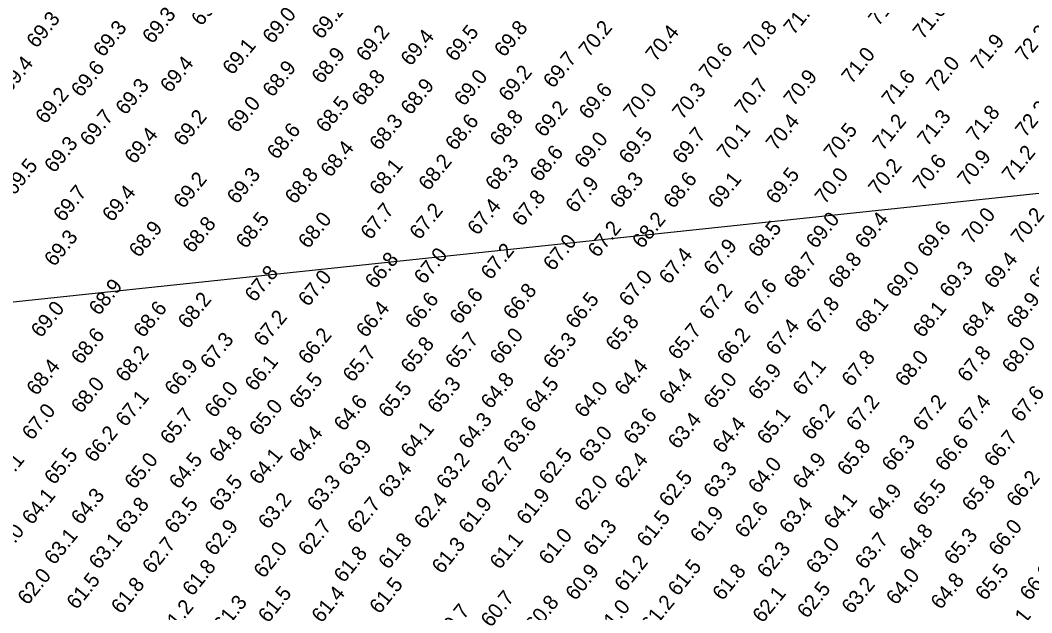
# Model space of a CAD drawing. Extents: x 401290 to 405690, y 1190598 to 1193998.
# Drawn here: x 403181 to 403862, y 1192215 to 1192614 of the extents above; entities that cross this region are included whole.
import ezdxf

# ---------------------------------------------------------------- set-up
doc = ezdxf.new("R2010")
doc.units = 0
doc.layers.add('C-CHAN-CNTR', color=7, linetype='Continuous')
doc.layers.add('V-TOPO-SOUN', color=7, linetype='Continuous')

msp = doc.modelspace()

# ---------------------------------------------------------------- linework, layer by layer
at = {"layer": 'C-CHAN-CNTR'}
msp.add_line((401937.03, 1192293.37), (404340.86, 1192548.17), dxfattribs=at)

# ---------------------------------------------------------------- texts
at = {"layer": 'V-TOPO-SOUN'}
for s, p in [('71.3 ', (403759.2, 1192610.02)), ('69.1 ', (403303.19, 1192610.02)), ('71.0 ', (403702.17, 1192604.02)), ('69.3 ', (403270.19, 1192598.02)), ('69.0 ', (403351.19, 1192598.02)), ('69.2 ', (403384.2, 1192601.04)), ('71.6 ', (403789.18, 1192601.04)), ('69.3 ', (403192.2, 1192595.03)), ('69.3 ', (403237.18, 1192589.03)), ('69.2 ', (403414.18, 1192586.01)), ('69.4 ', (403444.2, 1192583.02)), ('69.5 ', (403474.19, 1192586.01)), ('69.8 ', (403507.2, 1192589.03)), ('70.2 ', (403564.18, 1192589.03)), ('70.4 ', (403609.2, 1192586.01)), ('70.8 ', (403675.17, 1192589.03)), ('72.2 ', (403858.18, 1192586.01)), ('69.1 ', (403324.19, 1192577.02)), ('71.9 ', (403828.19, 1192580)), ('68.9 ', (403384.2, 1192571.02)), ('70.6 ', (403645.19, 1192574.03)), ('71.0 ', (403741.18, 1192571.02)), ('69.4 ', (403174.19, 1192565.01)), ('69.6 ', (403222.19, 1192562.03)), ('69.4 ', (403282.2, 1192565.01)), ('69.7 ', (403540.2, 1192568.03)), ('72.0 ', (403798.17, 1192565.01)), ('68.9 ', (403351.19, 1192562.03)), ('68.8 ', (403411.2, 1192556.02)), ('69.0 ', (403480.19, 1192556.02)), ('69.2 ', (403510.18, 1192559.01)), ('70.9 ', (403702.17, 1192556.02)), ('71.6 ', (403768.19, 1192556.02)), ('69.3 ', (403252.18, 1192550.02)), ('68.9 ', (403444.2, 1192550.02)), ('70.7 ', (403669.2, 1192550.02)), ('69.2 ', (403198.17, 1192544.01)), ('69.6 ', (403564.18, 1192547.03)), ('70.0 ', (403594.2, 1192547.03)), ('70.3 ', (403627.18, 1192547.03)), ('69.0 ', (403327.18, 1192538.01)), ('68.5 ', (403387.18, 1192538.01)), ('69.2 ', (403534.2, 1192535.02)), ('72.2 ', (403858.18, 1192535.02)), ('69.7 ', (403228.19, 1192529.02)), ('69.2 ', (403291.18, 1192529.02)), ('68.8 ', (403504.18, 1192529.02)), ('71.3 ', (403792.2, 1192529.02)), ('71.8 ', (403825.17, 1192532.01)), ('68.3 ', (403423.17, 1192526.04)), ('68.6 ', (403474.19, 1192526.04)), ('70.4 ', (403690.2, 1192526.04)), ('71.2 ', (403762.18, 1192526.04)), ('69.4 ', (403258.18, 1192517.01)), ('68.6 ', (403354.18, 1192520.03)), ('69.5 ', (403591.18, 1192517.01)), ('69.7 ', (403627.18, 1192517.01)), ('70.1 ', (403657.19, 1192520.03)), ('70.5 ', (403729.18, 1192520.03)), ('69.3 ', (403204.18, 1192511.01)), ('68.4 ', (403390.2, 1192508.02)), ('69.0 ', (403561.2, 1192514.03)), ('68.6 ', (403531.18, 1192505.01)), ('70.9 ', (403819.2, 1192502.02)), ('71.2 ', (403849.19, 1192505.01)), ('69.5 ', (403177.18, 1192496.02)), ('68.1 ', (403423.17, 1192496.02)), ('68.2 ', (403456.18, 1192499.03)), ('68.3 ', (403501.19, 1192499.03)), ('70.2 ', (403759.2, 1192496.02)), ('70.6 ', (403789.18, 1192499.03)), ('69.3 ', (403327.18, 1192490.01)), ('68.8 ', (403366.18, 1192490.01)), ('68.6 ', (403621.17, 1192487.03)), ('69.5 ', (403690.2, 1192490.01)), ('70.0 ', (403723.17, 1192490.01)), ('69.2 ', (403291.18, 1192487.03)), ('67.9 ', (403555.19, 1192484.01)), ('68.3 ', (403585.18, 1192487.03)), ('69.1 ', (403651.19, 1192487.03)), ('69.7 ', (403210.18, 1192478.04)), ('69.4 ', (403243.19, 1192478.04)), ('67.8 ', (403519.2, 1192475.02)), ('67.7 ', (403417.2, 1192466.03)), ('67.4 ', (403489.18, 1192469.01)), ('68.5 ', (403333.18, 1192460.02)), ('67.2 ', (403450.17, 1192466.03)), ('68.2 ', (403600.17, 1192460.02)), ('69.4 ', (403750.17, 1192460.02)), ('70.0 ', (403822.19, 1192463.01)), ('70.2 ', (403855.19, 1192463.01)), ('68.9 ', (403261.2, 1192454.02)), ('68.8 ', (403297.19, 1192457.01)), ('68.0 ', (403375.17, 1192460.02)), ('67.2 ', (403570.19, 1192454.02)), ('68.5 ', (403678.19, 1192454.02)), ('69.0 ', (403717.2, 1192460.02)), ('69.6 ', (403792.2, 1192454.02)), ('69.3 ', (403204.18, 1192448.02)), ('67.0 ', (403540.2, 1192445.03)), ('67.9 ', (403648.17, 1192442.01)), ('66.8 ', (403420.19, 1192433.02)), ('67.0 ', (403453.19, 1192436.01)), ('67.2 ', (403498.17, 1192439.03)), ('67.4 ', (403618.19, 1192436.01)), ('68.7 ', (403702.17, 1192433.02)), ('68.8 ', (403732.19, 1192433.02)), ('69.4 ', (403837.18, 1192433.02)), ('69.7 ', (403867.2, 1192433.02)), ('69.0 ', (403771.17, 1192427.02)), ('69.3 ', (403807.19, 1192427.02)), ('67.8 ', (403339.18, 1192424.03)), ('67.0 ', (403375.17, 1192421.02)), ('67.0 ', (403591.18, 1192421.02)), ('68.9 ', (403234.2, 1192415.01)), ('67.6 ', (403675.17, 1192415.01)), ('68.2 ', (403294.17, 1192406.02)), ('66.6 ', (403447.19, 1192406.02)), ('66.6 ', (403477.18, 1192409.01)), ('66.8 ', (403513.2, 1192412.03)), ('66.5 ', (403555.19, 1192406.02)), ('67.2 ', (403645.19, 1192412.03)), ('68.9 ', (403852.17, 1192406.02)), ('69.0 ', (403195.19, 1192400.02)), ('68.6 ', (403264.18, 1192400.02)), ('66.4 ', (403414.18, 1192400.02)), ('67.8 ', (403717.2, 1192403.04)), ('68.1 ', (403750.17, 1192403.04)), ('68.1 ', (403789.18, 1192400.02)), ('68.4 ', (403822.19, 1192400.02)), ('67.2 ', (403345.19, 1192394.01)), ('65.8 ', (403582.19, 1192391.03)), ('65.7 ', (403624.19, 1192385.03)), ('67.4 ', (403690.2, 1192388.01)), ('68.6 ', (403222.19, 1192382.01)), ('67.3 ', (403309.2, 1192379.02)), ('66.2 ', (403375.17, 1192382.01)), ('65.7 ', (403474.19, 1192379.02)), ('66.0 ', (403504.18, 1192382.01)), ('65.3 ', (403540.2, 1192379.02)), ('66.2 ', (403657.19, 1192382.01)), ('65.8 ', (403444.2, 1192376.04)), ('68.0 ', (403849.19, 1192376.04)), ('68.2 ', (403252.18, 1192370.03)), ('65.7 ', (403405.19, 1192370.03)), ('67.8 ', (403741.18, 1192367.01)), ('68.0 ', (403777.17, 1192367.01)), ('67.8 ', (403819.2, 1192370.03)), ('68.4 ', (403192.2, 1192361.01)), ('66.9 ', (403285.18, 1192361.01)), ('66.1 ', (403339.18, 1192364.03)), ('64.4 ', (403588.2, 1192361.01)), ('65.9 ', (403678.19, 1192358.02)), ('67.1 ', (403708.18, 1192361.01)), ('65.5 ', (403369.17, 1192352.02)), ('64.8 ', (403498.17, 1192352.02)), ('64.4 ', (403618.19, 1192355.01)), ('65.0 ', (403648.17, 1192352.02)), ('68.0 ', (403222.19, 1192349.03)), ('66.0 ', (403312.18, 1192346.02)), ('65.5 ', (403429.18, 1192346.02)), ('65.3 ', (403462.18, 1192349.03)), ('64.5 ', (403528.19, 1192349.03)), ('64.0 ', (403561.2, 1192346.02)), ('67.1 ', (403252.18, 1192340.01)), ('64.6 ', (403399.19, 1192337.03)), ('67.6 ', (403855.19, 1192343.03)), ('67.0 ', (403189.18, 1192331.02)), ('65.0 ', (403342.2, 1192334.01)), ('66.2 ', (403714.18, 1192331.02)), ('67.2 ', (403744.2, 1192337.03)), ('67.2 ', (403789.18, 1192337.03)), ('67.4 ', (403819.2, 1192337.03)), ('65.7 ', (403282.2, 1192328.04)), ('64.3 ', (403483.18, 1192325.02)), ('63.6 ', (403594.2, 1192328.04)), ('63.4 ', (403624.19, 1192325.02)), ('65.1 ', (403684.2, 1192328.04)), ('64.1 ', (403444.2, 1192319.01)), ('63.6 ', (403513.2, 1192322.03)), ('64.4 ', (403654.18, 1192322.03)), ('66.2 ', (403231.18, 1192316.03)), ('64.8 ', (403315.2, 1192316.03)), ('64.4 ', (403369.17, 1192316.03)), ('63.0 ', (403564.18, 1192316.03)), ('66.6 ', (403804.18, 1192310.03)), ('66.7 ', (403837.18, 1192313.01)), ('63.9 ', (403402.18, 1192307.01)), ('65.8 ', (403738.2, 1192307.01)), ('66.3 ', (403768.19, 1192310.03)), ('65.1 ', (403168.19, 1192298.02)), ('65.5 ', (403204.18, 1192301.04)), ('65.0 ', (403258.18, 1192298.02)), ('64.5 ', (403288.2, 1192298.02)), ('64.1 ', (403342.2, 1192301.04)), ('63.2 ', (403468.19, 1192298.02)), ('62.5 ', (403537.18, 1192301.04)), ('62.4 ', (403588.2, 1192298.02)), ('64.9 ', (403708.18, 1192298.02)), ('63.4 ', (403429.18, 1192292.01)), ('62.7 ', (403498.17, 1192295.03)), ('63.3 ', (403648.17, 1192292.01)), ('64.0 ', (403678.19, 1192295.03)), ('63.5 ', (403315.2, 1192283.02)), ('63.3 ', (403381.18, 1192283.02)), ('62.0 ', (403561.2, 1192283.02)), ('62.5 ', (403618.19, 1192286.01)), ('65.8 ', (403822.19, 1192283.02)), ('66.2 ', (403852.17, 1192286.01)), ('64.9 ', (403759.2, 1192277.02)), ('65.5 ', (403789.18, 1192280.01)), ('64.1 ', (403189.18, 1192274.03)), ('64.3 ', (403222.19, 1192274.03)), ('63.2 ', (403348.17, 1192271.02)), ('62.4 ', (403453.19, 1192271.02)), ('61.9 ', (403522.19, 1192274.03)), ('64.1 ', (403729.18, 1192271.02)), ('63.8 ', (403252.18, 1192268.03)), ('63.5 ', (403285.18, 1192268.03)), ('62.7 ', (403408.18, 1192268.03)), ('61.9 ', (403483.18, 1192268.03)), ('62.6 ', (403669.2, 1192265.01)), ('63.4 ', (403699.19, 1192268.03)), ('61.5 ', (403603.19, 1192259.01)), ('61.9 ', (403639.18, 1192262.03)), ('63.0 ', (403168.19, 1192250.02)), ('62.9 ', (403312.18, 1192253.04)), ('62.7 ', (403375.17, 1192253.04)), ('61.3 ', (403567.2, 1192253.04)), ('64.8 ', (403780.19, 1192250.02)), ('66.0 ', (403840.2, 1192253.04)), ('63.1 ', (403204.18, 1192247.03)), ('63.1 ', (403234.2, 1192244.01)), ('61.8 ', (403429.18, 1192244.01)), ('61.1 ', (403504.18, 1192244.01)), ('61.0 ', (403537.18, 1192247.03)), ('63.7 ', (403750.17, 1192244.01)), ('65.3 ', (403810.18, 1192247.03)), ('62.7 ', (403270.19, 1192241.03)), ('62.0 ', (403345.19, 1192238.01)), ('61.3 ', (403465.2, 1192241.03)), ('62.3 ', (403684.2, 1192238.01)), ('63.0 ', (403717.2, 1192241.03)), ('61.8 ', (403399.19, 1192235.03)), ('61.2 ', (403588.2, 1192229.02)), ('61.8 ', (403297.19, 1192226.04)), ('60.9 ', (403555.19, 1192223.02)), ('61.5 ', (403624.19, 1192226.04)), ('61.8 ', (403654.18, 1192223.02)), ('65.5 ', (403831.18, 1192223.02)), ('66.2 ', (403861.2, 1192223.02)), ('62.0 ', (403186.2, 1192220.03)), ('61.5 ', (403219.17, 1192217.01)), ('64.0 ', (403771.17, 1192220.03)), ('64.8 ', (403801.19, 1192217.01)), ('61.8 ', (403249.19, 1192214.03)), ('61.5 ', (403348.17, 1192208.02)), ('61.4 ', (403384.2, 1192208.02)), ('61.5 ', (403423.17, 1192214.03)), ('62.5 ', (403711.2, 1192211.01)), ('63.2 ', (403741.18, 1192214.03)), ('61.3 ', (403318.19, 1192202.02)), ('60.7 ', (403498.17, 1192205.01)), ('60.8 ', (403528.19, 1192202.02)), ('61.2 ', (403606.18, 1192202.02)), ('62.1 ', (403681.18, 1192208.02)), ('61.2 ', (403282.2, 1192199.03)), ('60.7 ', (403468.19, 1192196.02)), ('61.0 ', (403576.19, 1192199.03)), ('65.1 ', (403846.17, 1192193.03))]:
    msp.add_text(s, height=9.996, rotation=51.05, dxfattribs=at).set_placement(p)

doc.saveas('drawing.dxf')
